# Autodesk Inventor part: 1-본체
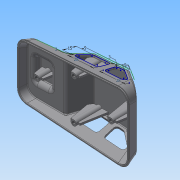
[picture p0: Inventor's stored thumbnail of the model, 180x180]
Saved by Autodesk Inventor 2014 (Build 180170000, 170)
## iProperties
Created: 2015-05
Part Number: 1-본체
Material: Generic
Document SubType Name: Modeling
Designer: Administrator
Density: 1 g/cm^3
Appearance: Default
Author: Administrator
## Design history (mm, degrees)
sketch "스케치1"
  geometry: L1 (-61, 0)-(61, 0); L2 (61, 0)-(58.321, 10); L3 (58.321, 10)-(31, 30); L4 (31, 30)-(-7.174, 30); L5 (-7.174, 30)-(-19, 11.075); L6 (-19, 11.075)-(-58.588, 9); L7 (-58.588, 9)-(-61, 0); 2 further points
  constraints: 14 end point, 2 coincident, 1 horizontal, 1 midpoint, 1 parallel
  dimensions: "d0" = 122 distance of L1.start L1.end; "d1" = 105 deg angle of L1 L2; "d2" = 20 distance from line of L2.end L4; "d3" = 30 distance between parallel lines of L1 L4; "d4" = 30 horizontal distance of L1.end L3.end; "d5" = 42 horizontal distance of L5.end L1.start; "d6" = 125 deg angle of L5 L6; "d7" = 105 deg angle of L1 L7; "d8" = 3 deg angle of L1 L6; "d9" = 9 vertical distance of L1.start L6.end
extrude "돌출1" new body sketch "스케치1" stored distance "d10" = 76; taper "d11" = 0 deg
sketch "스케치12"
  geometry: L1 (76, -10.353)-(0, -10.353) reference; L2 (76, 36.27)-(0, 36.27) reference; L3 (76, -10.353)-(63.508, 36.27); L4 (0, -10.353)-(12.492, 36.27); L5 (76, 36.27)-(76, -10.353); L6 (0, 36.27)-(0, -10.353); 1 further point
  constraints: 8 end point, 2 point on line, 1 parallel, 1 perpendicular
  dimensions: "d110" = 105 deg angle of L1 L3; "d111" = 105 deg angle of L1 L4
extrude "돌출11" cut sketch "스케치12" stored distance "d112" = 2; taper "d113" = 0 deg
fillet "모깎기2" dims "d17" = 12
fillet "모깎기3" dims "d19" = 3
fillet "모깎기1" dims "d16" = 3
node "작업 평면3"
sketch "스케치6"
  geometry: L1 (-20.544, 10.994)-(-48.185, 9.545) reference; L2 (-56.412, 9.114)-(-48.185, 9.545) reference; L3 (-50.184, 0)-(-61, 0) reference; L4 (-51.556, 9.369)-(-50, 14.457); L5 (-50, 14.457)-(-33.635, 15.315); L6 (-33.635, 15.315)-(-31.556, 10.417); 2 further points
  constraints: 6 end point, 2 point on line, 1 coincident, 1 equal length, 1 parallel
  dimensions: "d119" = 11 horizontal distance of point (-61, 0) L4.end; "d120" = 20 horizontal distance of L6.end L4.start; "d121" = 70 deg angle of L6 L1; "d122" = 5 distance between parallel lines of L1 L5
extrude "돌출5" join sketch "스케치6" distance "d42" = 26; taper "d43" = 0 deg
fillet "모깎기6" dims "d123" = 3
fillet "모깎기5" dims "d45" = 3
feature "쉘1" dims "d12" = 2
sketch "스케치2"
  geometry: L1 (2.071, -56.599)-(2.071, -19.401) reference; L2 (119.929, -12.567)-(119.929, -63.433) reference; L3 (0, -19.276)-(0, -56.724) reference; L4 (10.816, -68.289)-(109.577, -75.138) reference; L5 (122, -63.577)-(122, -12.423) reference; L6 (109.577, -0.862)-(10.816, -7.711) reference; L7 (1, -19.276)-(1, -56.724); L8 (10.885, -67.292)-(109.646, -74.141); L9 (121, -63.577)-(121, -12.423); L10 (109.646, -1.859)-(10.885, -8.708); L11 (109.577, -2.932)-(11.084, -9.763) reference; L12 (2.071, -19.401)-(2.071, -56.599) reference; L13 (11.084, -66.237)-(109.577, -73.068) reference; L14 (119.929, -63.433)-(119.929, -12.567) reference; L15 (10.816, -7.711)-(109.577, -0.862) reference; L16 (122, -12.423)-(122, -63.577) reference; L17 (109.577, -75.138)-(10.816, -68.289) reference; L18 (0, -56.724)-(0, -19.276) reference; L19 (109.577, -2.932)-(11.084, -9.763) reference; L20 (2.071, -19.401)-(2.071, -56.599) reference; L21 (11.084, -66.237)-(109.577, -73.068) reference; L22 (119.929, -63.433)-(119.929, -12.567) reference; L23 (10.816, -7.711)-(109.577, -0.862) reference; L24 (122, -12.423)-(122, -63.577) reference; L25 (109.577, -75.138)-(10.816, -68.289) reference; L26 (0, -56.724)-(0, -19.276) reference; 21 further points; 20 other entities
  constraints: 8 end point, 7 parallel, 32 other
  dimensions: "d124" = 1 distance between parallel lines of L10 L6
  node "절단 모서리 투영1"
  node "절단 모서리 투영2"
extrude "돌출2" join sketch "스케치2" distance "d14" = 1; taper "d15" = 0 deg
node "작업 평면1"
node "작업 평면2"
sketch "스케치3"
  geometry: L1 (66.511, -60.577)-(66.511, -9.423) reference; C1 r 3 at (45.511, -35); C2 r 3 at (5.511, -57); C3 r 3 at (-34.489, -35); C4 r 3 at (5.511, -13); 3 further points
  constraints: 4 centre point, 3 equal radius, 2 horizontal alignment, 1 vertical alignment
  dimensions: "d21" = 21 distance from line of L1 C1.centre; "d22" = 40 horizontal distance of C2.centre C1.centre; "d23" = 40 horizontal distance of C2.centre C3.centre; "d24" = 6 diameter of C1; "d26" = 44 distance of C4.centre C2.centre; "d27" = 22 distance of point (5.511, -35) C2.centre
extrude "돌출3" join sketch "스케치3" stored distance "d28" = 1; taper "d29" = 0 deg
sketch "스케치4"
  geometry: L1 (-37, 0)-(-37, 13.136) reference; L2 (-43, 0)-(-43, 12.821) reference; L3 (37, 0)-(37, 23.129) reference; L4 (43, 0)-(43, 18.737) reference; L5 (37, 0)-(36.939, 1.753); L6 (36.939, 1.753)-(35, 1.753); L7 (35, 1.753)-(30.019, 30); L8 (43, 0)-(43.061, 1.753); L9 (43.061, 1.753)-(45, 1.753); L10 (45, 1.753)-(47.811, 17.694); L11 (-37, 0)-(-36.93, 2); L12 (-36.93, 2)-(-35, 2); L13 (-35, 2)-(-32.945, 13.652); L14 (-43, 0)-(-43.07, 2); L15 (-43.07, 2)-(-45, 2); L16 (-45, 2)-(-47.222, 14.603); L17 (-36.096, 15.186)-(-47.539, 14.586) reference; L18 (30.019, 30)-(-5.511, 30) reference; L19 (45.877, 19.109)-(57.468, 10.624) reference; L20 (45.877, 19.109)-(31.791, 29.421) reference; L21 (48.577, 0)-(-50.184, 0) reference; L22 (-43, 0)-(-37, 0); L23 (37, 0)-(43, 0); L24 (-47.222, 14.603)-(-35.732, 15.205); L25 (47.811, 17.694)-(31.791, 29.421); A1 r 3 centre (-47.745, 11.571) between (-47.902, 14.567) and (-50.614, 12.448) reference; A2 r 3 centre (-35.575, 12.209) between (-32.814, 13.381) and (-35.732, 15.205) reference; A3 r 3 centre (30.019, 27) between (31.791, 29.421) and (30.019, 30) reference; A4 r 3 centre (-35.575, 12.209) between (-32.945, 13.652) and (-35.732, 15.205); A5 r 3 centre (30.019, 27) between (31.791, 29.421) and (30.019, 30); 3 further points; 1 other entity
  constraints: 33 end point, 5 collinear, 5 point on circle, 4 equal length, 3 tangent, 2 centre point, 2 parallel, 2 point on line, 1 perpendicular, 2 other
  dimensions: "d55" = 10 distance of L6.end L9.end; "d56" = 10 deg angle of L3 L7; "d57" = 10 deg angle of L10 L4; "d59" = 2 deg angle of L11 L1; "d60" = 2 deg angle of L2 L14; "d62" = 10 distance of L12.end L15.end; "d63" = 10 deg angle of L2 L16; "d66" = 4 deg angle of L8 L5; "d125" = 2 distance between parallel lines of L21 L12; "d126" = 3 radius of A5
extrude "돌출12" join sketch "스케치4" stored distance "d127" = 2; taper "d128" = 0 deg
extrude "돌출13" join sketch "스케치4" stored distance "d129" = 2; taper "d130" = 0 deg
node "작업 평면4"
sketch "스케치7"
  geometry: L1 (-3, 0)-(-3, 28) reference; L2 (3, 0)-(3, 28) reference; L3 (3, 0)-(3.07, 2); L4 (3.07, 2)-(5, 2); L5 (-3, 0)-(-3.07, 2); L6 (-3.07, 2)-(-5, 2); L7 (-5, 2)-(-9.329, 26.551); L8 (5, 2)-(9.937, 30); L9 (48.577, 0)-(-50.184, 0) reference; L10 (-3, 0)-(3, 0); L11 (30.019, 30)-(-5.511, 30) reference; L12 (-8.055, 28.59)-(-18.172, 12.399) reference; L13 (-9.329, 26.551)-(-8.055, 28.59); L14 (-5.511, 30)-(9.937, 30); A1 r 3 centre (-5.511, 27) between (-5.511, 30) and (-8.055, 28.59) reference; A2 r 3 centre (-5.511, 27) between (-5.511, 30) and (-8.055, 28.59); 1 further point
  constraints: 18 end point, 3 point on circle, 2 collinear, 2 equal length, 2 tangent, 1 centre point, 1 concentric
  dimensions: "d75" = 2 deg angle of L1 L5; "d76" = 2 deg angle of L3 L2; "d78" = 10 distance of L4.end L6.end; "d79" = 10 deg angle of L2 L8; "d80" = 10 deg angle of L7 L1; "d131" = 2 distance between parallel lines of L9 L4; "d132" = 30 distance from line of L8.end L9; "d133" = 26.55145 distance from line of L7.end L9
extrude "돌출14" join sketch "스케치7" stored distance "d134" = 2; taper "d135" = 0 deg
sketch "스케치8"
  geometry: L1 (48.511, -36)-(48.34, -36) reference; L2 (48.511, -36)-(48.511, -34) reference; L3 (48.34, -34)-(48.511, -34) reference; L4 (42.511, -34)-(42.683, -34) reference; L5 (42.511, -34)-(42.511, -36) reference; L6 (42.683, -36)-(42.511, -36) reference; L7 (2.683, -56)-(2.511, -56) reference; L8 (2.511, -58)-(2.511, -56) reference; L9 (2.511, -58)-(2.683, -58) reference; L10 (8.34, -58)-(8.511, -58) reference; L11 (8.511, -56)-(8.511, -58) reference; L12 (8.511, -56)-(8.34, -56) reference; L13 (-31.489, -36)-(-31.66, -36) reference; L14 (-31.489, -34)-(-31.489, -36) reference; L15 (-31.66, -34)-(-31.489, -34) reference; L16 (-37.489, -34)-(-37.317, -34) reference; L17 (-37.489, -36)-(-37.489, -34) reference; L18 (-37.317, -36)-(-37.489, -36) reference; A1 r 3 centre (5.511, -13) between (8.34, -12) and (2.683, -12) reference; A2 r 3 centre (-34.489, -35) between (-31.66, -34) and (-37.317, -34) reference; A3 r 3 centre (5.511, -57) between (2.683, -58) and (8.34, -58) reference; A4 r 3 centre (45.511, -35) between (48.34, -34) and (42.683, -34) reference; A5 r 3 centre (45.511, -35) between (42.683, -36) and (48.34, -36) reference; A6 r 3 centre (5.511, -57) between (8.34, -56) and (2.683, -56) reference; A7 r 3 centre (-34.489, -35) between (-37.317, -36) and (-31.66, -36) reference; 5 further points
  constraints: 1 coincident
hole "구멍1" sketch "스케치8" at (-34.489, -35), (5.511, -13), (45.511, -35), (5.511, -57) diameter "d83" = 3.242; stored, may be unused: countersink angle "d87" = 90 deg, drill point angle "d89" = 118 deg; dims "d84" = 9, "d85" = 4, "d86" = 2, "d88" = 11
sketch "스케치9"
  geometry: L1 (1.83, 7.539)-(32.619, 9.203) reference; L2 (44.082, 28.66)-(79.698, 28.66) reference; L3 (32.619, 9.203)-(44.082, 28.66) reference; L4 (79.894, 25.971)-(91.983, 16.971); L5 (39.107, 16.088)-(44.409, 25.088); L6 (46.994, 26.565)-(61.442, 26.565); L7 (41.692, 11.565)-(61.442, 11.565); L8 (79.698, 31.565)-(44.082, 31.565) reference; L9 (95.77, 20.385)-(81.466, 31.035) reference; L10 (64.442, 23.565)-(64.442, 14.565); L11 (78.103, 26.565)-(73.6, 26.565); L12 (70.604, 23.403)-(71.091, 14.403); L13 (74.086, 11.565)-(90.191, 11.565); A1 r 3 centre (61.442, 23.565) between (64.442, 23.565) and (61.442, 26.565); A2 r 3 centre (61.442, 14.565) between (61.442, 11.565) and (64.442, 14.565); A3 r 3 centre (41.692, 14.565) between (39.107, 16.088) and (41.692, 11.565); A4 r 3 centre (46.994, 23.565) between (46.994, 26.565) and (44.409, 25.088); A5 r 3 centre (73.6, 23.565) between (73.6, 26.565) and (70.604, 23.403); A6 r 3 centre (74.086, 14.565) between (71.091, 14.403) and (74.086, 11.565); A7 r 3 centre (90.191, 14.565) between (90.191, 11.565) and (91.983, 16.971); A8 r 3 centre (78.103, 23.565) between (79.894, 25.971) and (78.103, 26.565); 4 further points
  constraints: 16 end point, 16 point on circle, 16 tangent, 10 point on line, 8 centre point, 5 equal radius, 2 parallel, 2 perpendicular, 1 vertical, 1 other
  dimensions: "d137" = 5 distance between parallel lines of L6 L8; "d138" = 5 distance between parallel lines of L9 L4; "d139" = 15 distance from line of point (36.442, 11.565) L6; "d141" = 3 radius of A1; "d142" = 28 distance from line of point (36.442, 11.565) L10; "d143" = 3 radius of A3; "d144" = 28 distance of point (99.244, 11.565) point (71.244, 11.565); "d145" = 3 radius of A5
extrude "돌출9" cut sketch "스케치9" stored distance "d98" = 2; taper "d99" = 0 deg
sketch "스케치10"
  geometry: A1 r 4 centre (5, 0) between (9, 0) and (1, 0); A2 r 4 centre (16, 0) between (20, 0) and (12, 0); A3 r 4 centre (36, 0) between (40, 0) and (32, 0); A4 r 4 centre (47, 0) between (51, 0) and (43, 0); 3 further points
  constraints: 8 point on circle, 4 centre point, 3 equal radius, 13 other
  dimensions: "d100" = 11 distance of A2.centre A1.centre; "d101" = 20 distance of A3.centre A2.centre; "d102" = 11 distance of A4.centre A3.centre; "d103" = 4 radius of A2; "d104" = 10 horizontal distance of point (26, 15.788) A2.centre
extrude "돌출10" join sketch "스케치10" distance "d105" = 2; taper "d106" = 0 deg
sketch "스케치11"
  geometry: L1 (66.511, 60.577)-(66.511, 9.423) reference; 4 further points
  constraints: 1 horizontal alignment, 1 other
  dimensions: "d107" = 50 distance from line of point (16.511, 35) L1
feature "엠보싱1" sketch "스케치11" dims "d0" = 122, "d1" = 105 deg, "d2" = 20, "d3" = 30, "d4" = 30, "d5" = 42, "d6" = 125 deg, "d7" = 105 deg, "d8" = 3 deg, "d9" = 9, "d108" = 0.5, "d109" = 0
node "솔리드1"
mirror "대칭1"
mirror "대칭2"
node "투영된 루프1"
node "투영된 루프2"
node "투영된 루프3"
other parameters: "d30" = 13, "d37" = 13, "d74" = 22
